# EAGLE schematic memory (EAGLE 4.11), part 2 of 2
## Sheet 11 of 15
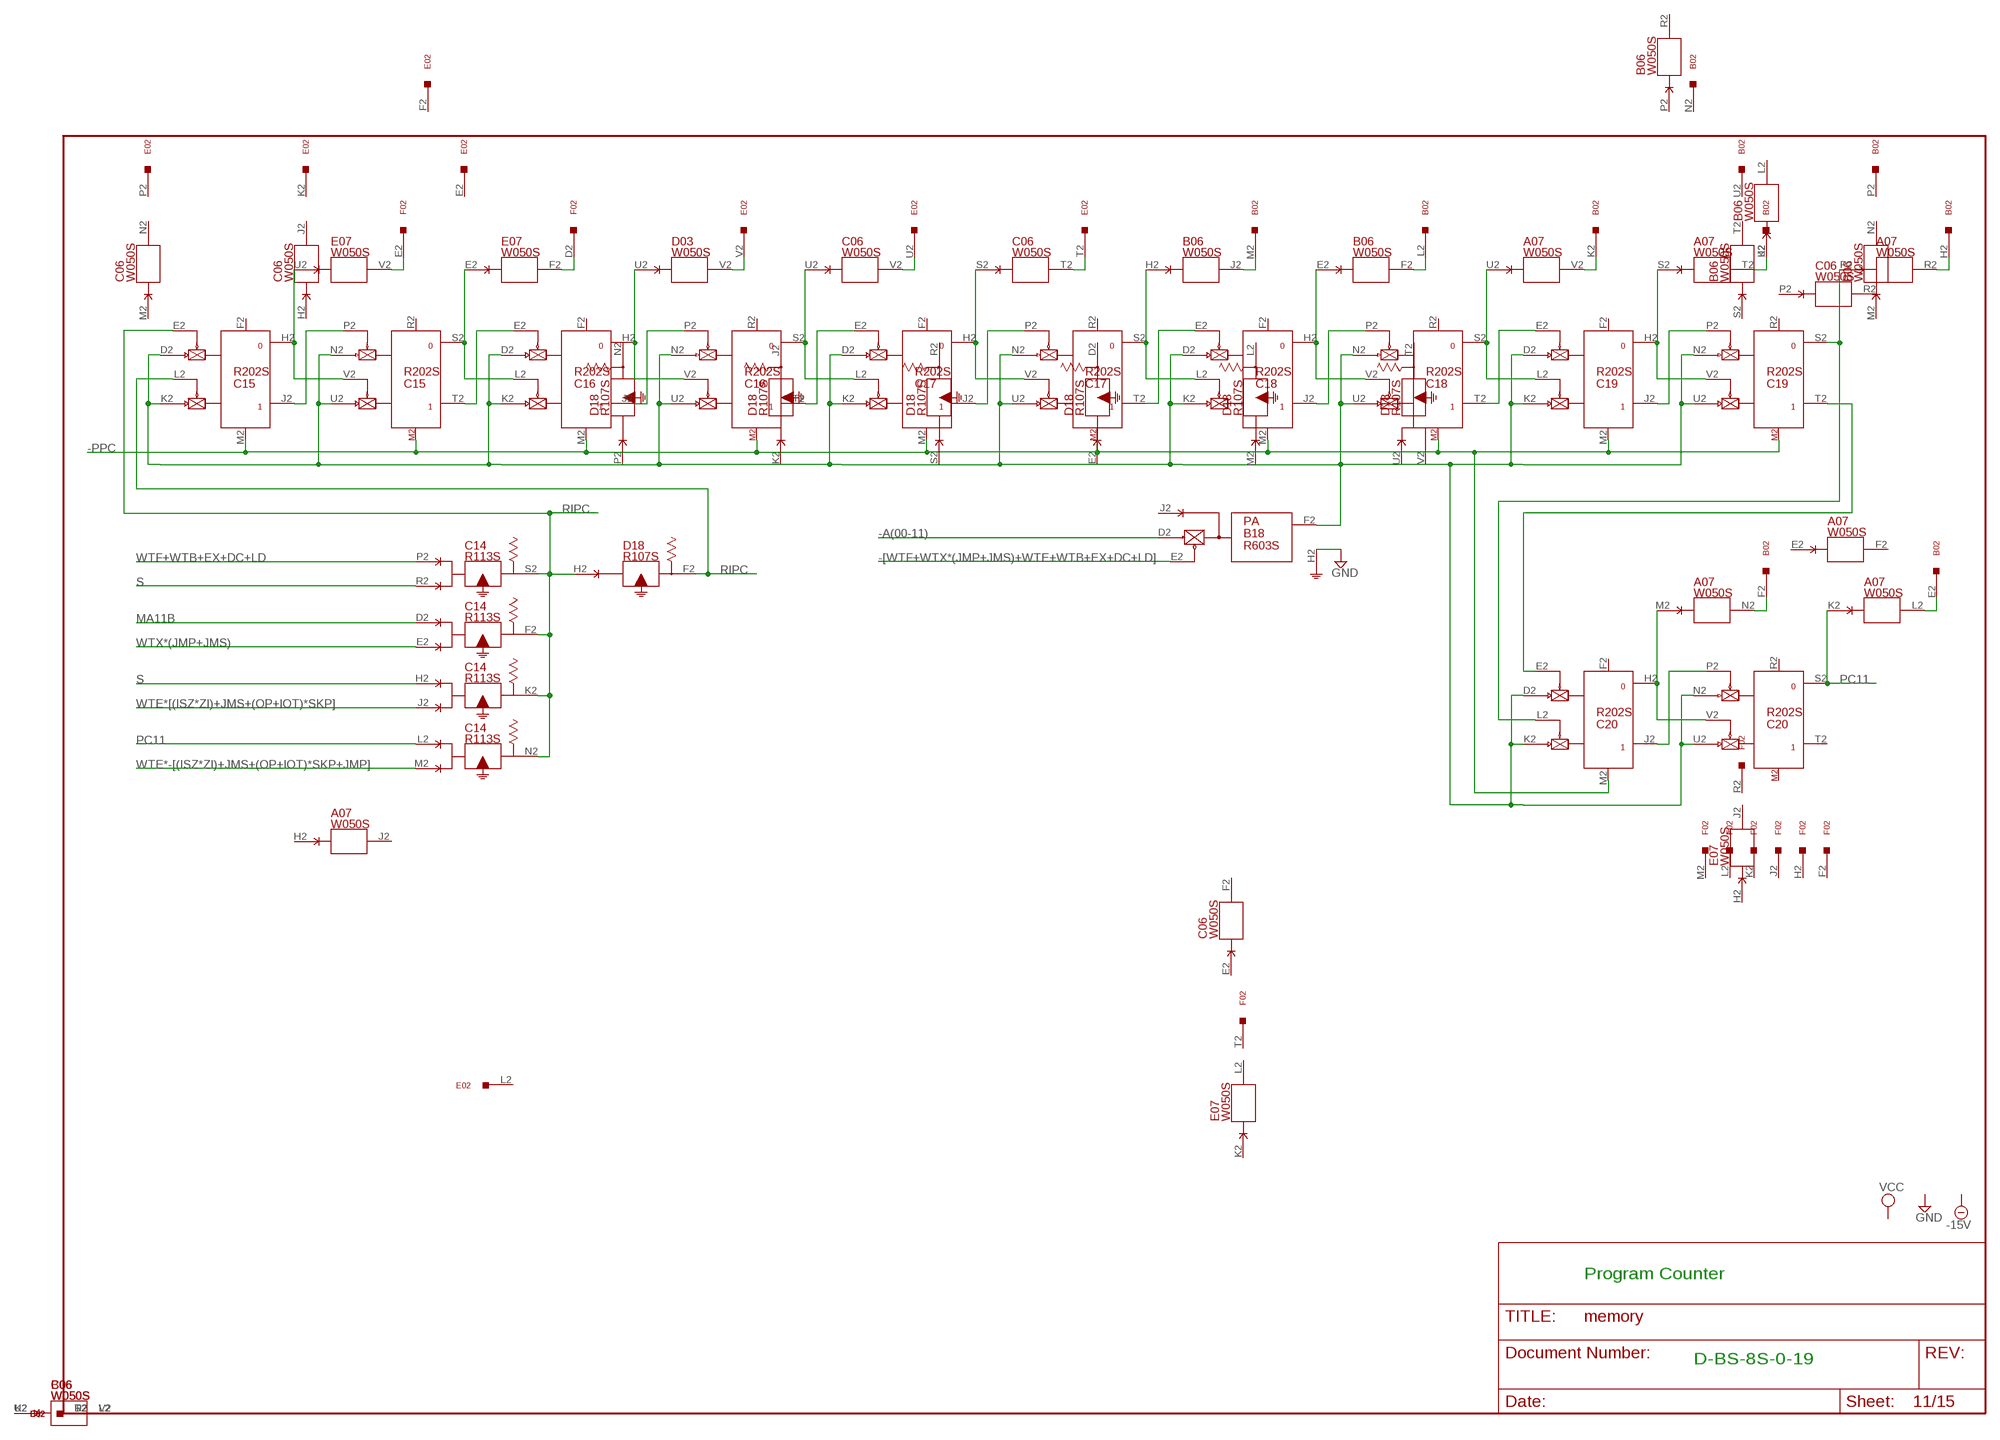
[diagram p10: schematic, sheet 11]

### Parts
C15  R202S  [H807S]
C16  R202S  [H807S]
C17  R202S  [H807S]
C18  R202S  [H807S]
C19  R202S  [H807S]
C20  R202S  [H807S]
D03  W050S  [H807S]

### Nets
-[WTF+WTX*(JMP+JMS)+WTE+WTB+EX+DC+LD]: B18.E2(F:EN0) ; also sheet 6
-A(00-11): B18.D2(F:PU0) ; also sheet 1,3,4,5,7,9,12
-PPC: C15.M2(J:SET) C16.M2(J:SET) C17.M2(J:SET) C18.M2(J:SET) C19.M2(J:SET) C20.M2(J:SET) ; also sheet 4,6,8,10,15
-RIPC: C14.F2(F:O$1) C14.K2(K:O$1) C14.N2(N:O$1) C14.S2(S:O$1) C15.E2(J:EN0) D18.H2(F:I$1)
GND [Supply]: B18.H2(F:G) ; also sheet 1,2,3,4,5,6,7,8,9,10,12,14,15
MA11B: C14.D2(F:I$1) ; also sheet 5
N$245: C15.H2 C15.V2(T:EN1) E07.U2(V:I$1)
N$246: C15.J2 C15.P2(T:EN0)
N$247: B18.F2(F:O) C15.D2(J:PU0) C15.K2(J:PU1) C15.N2(T:PU0) C15.U2(T:PU1) C16.D2(J:PU0) C16.K2(J:PU1) C16.N2(T:PU0) C16.U2(T:PU1) C17.D2(J:PU0) C17.K2(J:PU1) C17.N2(T:PU0) C17.U2(T:PU1) C18.D2(J:PU0) C18.K2(J:PU1) C18.N2(T:PU0) C18.U2(T:PU1) C19.D2(J:PU0) C19.K2(J:PU1) C19.N2(T:PU0) C19.U2(T:PU1) C20.D2(J:PU0) C20.K2(J:PU1) C20.N2(T:PU0) C20.U2(T:PU1)
N$248: C16.H2 C16.V2(T:EN1) D03.U2(V:I$1)
N$249: C16.J2 C16.P2(T:EN0)
N$250: A07.L2(L:O$1) B02.E2
N$251: C06.S2(T:I$1) C17.H2 C17.V2(T:EN1)
N$252: C17.J2 C17.P2(T:EN0)
N$253: A07.N2(N:O$1) B02.F2
N$254: B06.E2(F:I$1) C18.H2 C18.V2(T:EN1)
N$255: C18.J2 C18.P2(T:EN0)
N$256: A07.V2(V:O$1) B02.K2
N$257: A07.S2(T:I$1) C19.H2 C19.V2(T:EN1)
N$258: C19.J2 C19.P2(T:EN0)
N$259: A07.T2(T:O$1) B02.J2
N$260: A07.M2(N:I$1) C20.H2 C20.V2(T:EN1)
N$261: C20.J2 C20.P2(T:EN0)
N$262: A07.R2(R:O$1) B02.H2
N$263: C15.S2 C16.L2(J:EN1) E07.E2(F:I$1)
N$264: C15.T2 C16.E2(J:EN0)
N$265: C06.U2(V:I$1) C16.S2 C17.L2(J:EN1)
N$266: C16.T2 C17.E2(J:EN0)
N$267: B06.H2(J:I$1) C17.S2 C18.L2(J:EN1)
N$268: A07.U2(V:I$1) C18.S2 C19.L2(J:EN1)
N$269: C18.T2 C19.E2(J:EN0)
N$270: C17.T2 C18.E2(J:EN0)
N$271: A07.P2(R:I$1) C19.S2 C20.L2(J:EN1)
N$272: C19.T2 C20.E2(J:EN0)
N$273: B02.M2 B06.J2(J:O$1)
N$274: B02.L2 B06.F2(F:O$1)
N$275: D03.V2(V:O$1) E02.V2
N$276: C06.V2(V:O$1) E02.U2
N$277: C06.T2(T:O$1) E02.T2
N$278: E07.V2(V:O$1) F02.E2
N$279: E07.F2(F:O$1) F02.D2
PC11: A07.K2(L:I$1) C14.L2(N:I$1) C20.S2 ; also sheet 1,5,7
RIPC: C15.L2(J:EN1) D18.F2(F:O$1)
S: C14.H2(K:I$1) C14.R2(S:I$2) ; also sheet 1,5,7,12
WTE*-[(ISZ*ZI)+JMS+(OP+IOT)*SKP+JMP]: C14.M2(N:I$2) ; also sheet 5,6
WTE*[(ISZ*ZI)+JMS+(OP+IOT)*SKP]: C14.J2(K:I$2) ; also sheet 5,6
WTF+WTB+EX+DC+LD: C14.P2(S:I$1) ; also sheet 6
WTX*(JMP+JMS): C14.E2(F:I$2) ; also sheet 5,6,15
Unconnected: C15.F2(J:RESET) C15.R2(T:RESET) C16.F2(J:RESET) C16.R2(T:RESET) C17.F2(J:RESET) C17.R2(T:RESET) C18.F2(J:RESET) C18.R2(T:RESET) C19.F2(J:RESET) C19.R2(T:RESET) C20.F2(J:RESET) C20.R2(T:RESET) C20.T2 D18.V2(T:I$2)

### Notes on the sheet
- Program Counter
- D-BS-8S-0-19

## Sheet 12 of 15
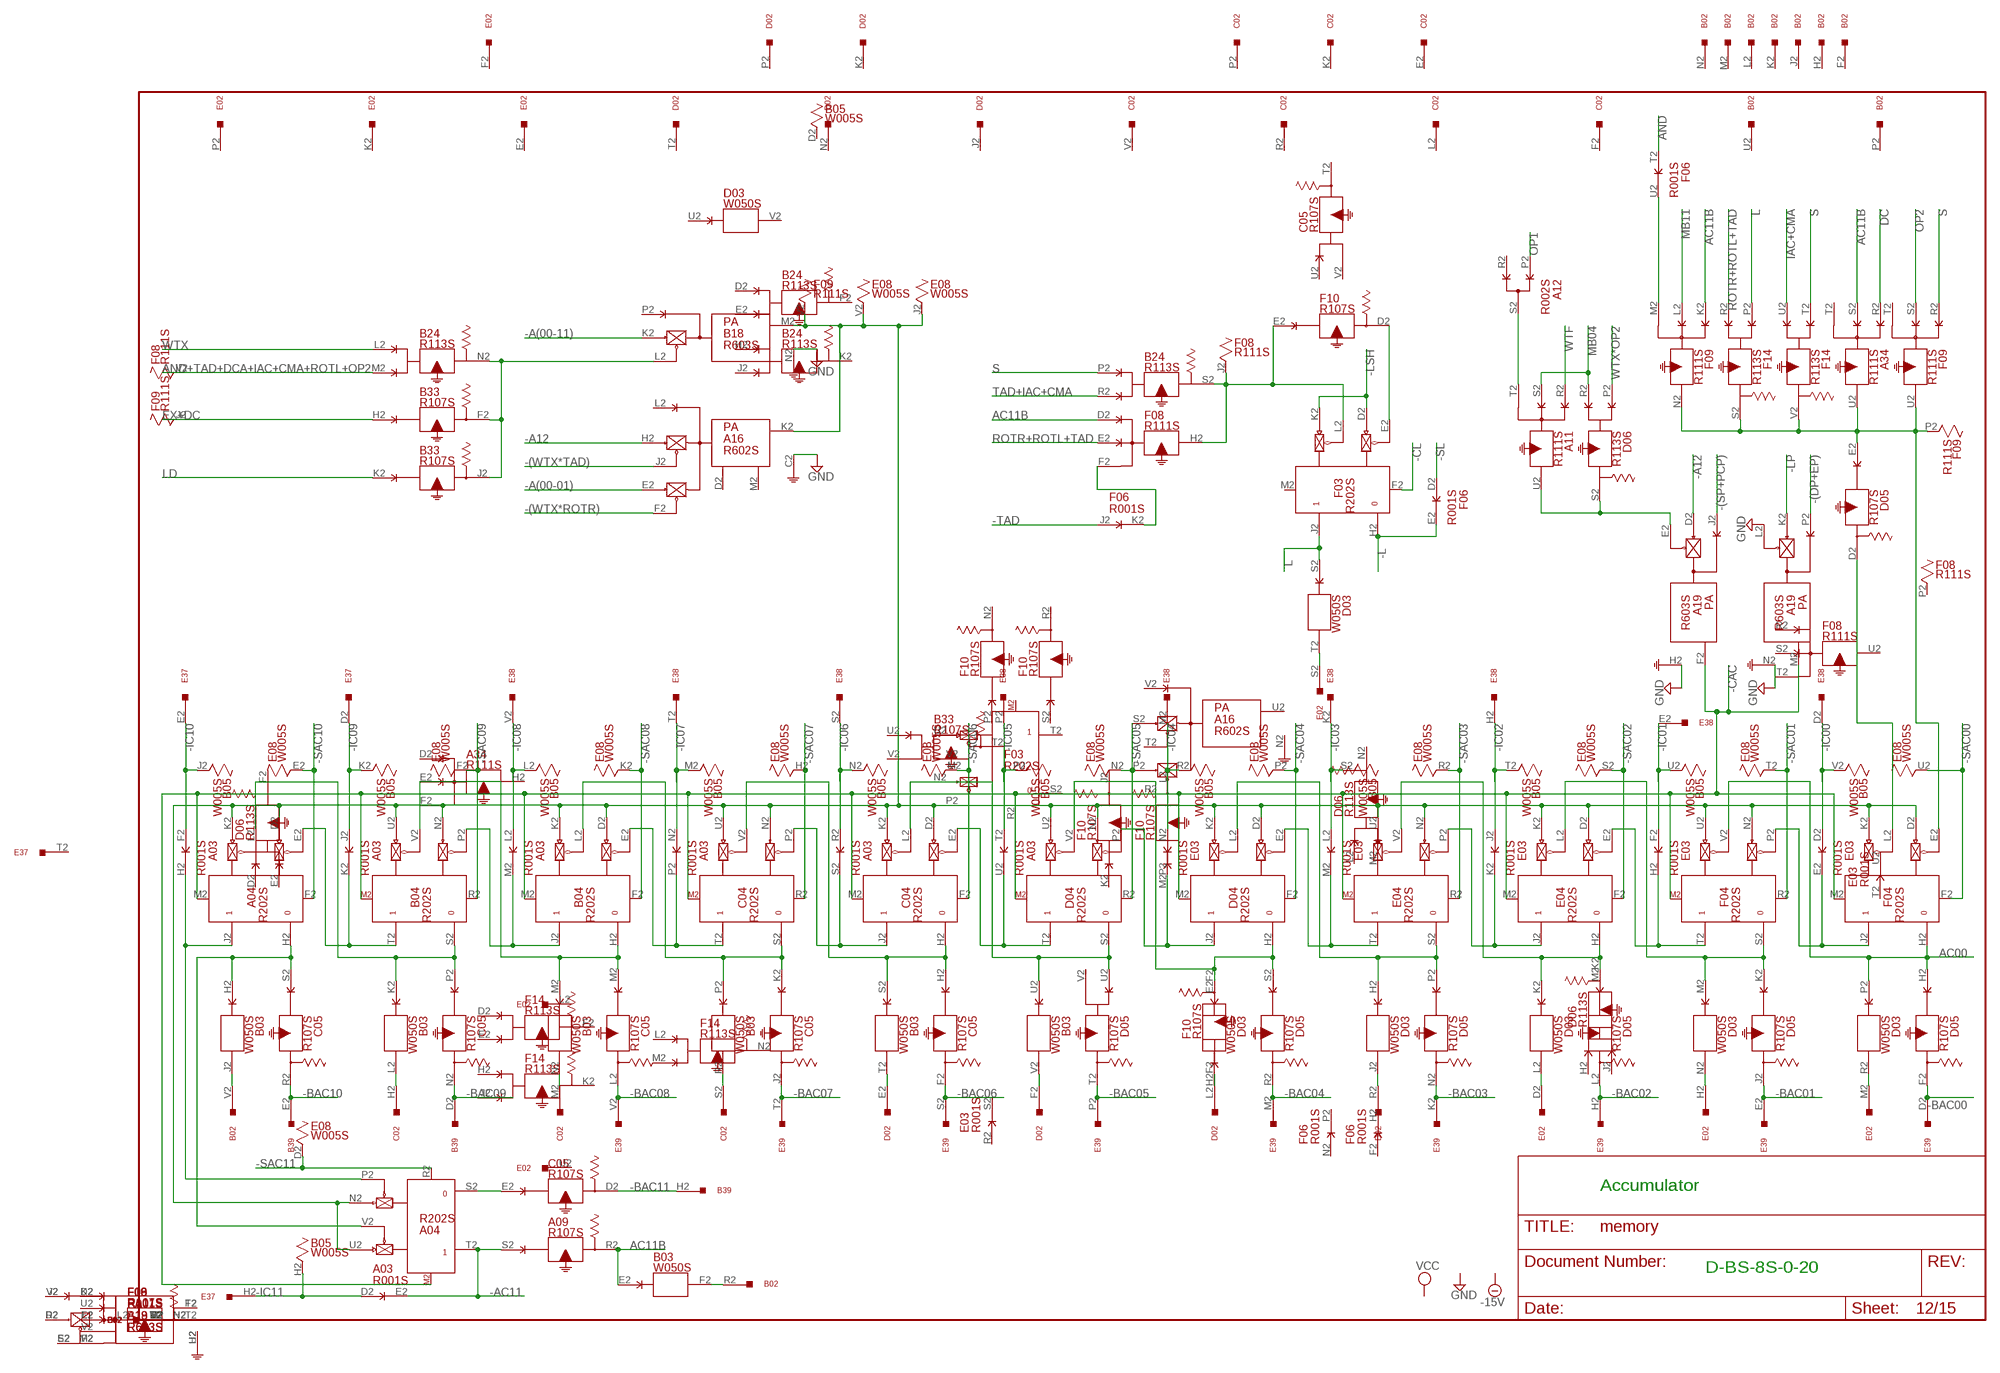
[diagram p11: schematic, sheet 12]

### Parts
A03  R001S  [H807S]
A04  R202S  [H807S]
A19  R603S  [H807S]
B03  W050S  [H807S]
B04  R202S  [H807S]
C04  R202S  [H807S]
D04  R202S  [H807S]
D05  R107S  [H807S]
E04  R202S  [H807S]
E08  W005S  [H807S]
E38  W028S  [H807S]
E39  W028S  [H807S]
F04  R202S  [H807S]

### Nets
-(DP+EP): A19.P2(M:I$1) ; also sheet 4,6,8
-(SP+PCP): A19.J2(F:I$1) ; also sheet 1,3,7,8,10,14,15
-(WTX*ROTR): A16.F2(K:F) ; also sheet 3,6
-(WTX*TAD): A16.J2(K:J) ; also sheet 6
-A12: A16.H2(K:H) A19.D2(F:PU0) ; also sheet 1,3,4,6,8,10,15
-A(00-01): A16.E2(K:E) ; also sheet 3,4
-A(00-11): B18.K2(M:PU0) ; also sheet 1,3,4,5,7,9,11
-AC11: A03.E2(E:E) A04.T2 A09.S2(R:I$1) ; also sheet 7
-BAC00: D05.F2(F:O$1) E39.D2
-BAC01: D05.J2(J:O$1) E39.E2
-BAC02: D05.L2(L:O$1) E39.H2
-BAC03: D05.N2(N:O$1) E39.K2
-BAC04: D05.R2(R:O$1) E39.M2
-BAC05: D05.T2(T:O$1) E39.P2
-BAC06: C05.F2(F:O$1) E39.S2
-BAC07: C05.J2(J:O$1) E39.T2
-BAC08: C05.L2(L:O$1) E39.V2
-BAC09: B39.D2 C05.N2(N:O$1)
-BAC10: B39.E2 C05.R2(R:O$1)
-BAC11: B39.H2 C05.D2(D:O$1)
-CAC: A04.M2(J:SET) A19.F2(F:O) A19.M2(M:O) B04.M2(J:SET) C04.M2(J:SET) D04.M2(J:SET) E04.M2(J:SET) F04.M2(J:SET) ; also sheet 10
-CL: F03.F2(J:RESET) ; also sheet 3
-IC00: B05.V2 E03.D2(E:D) E38.D2
-IC01: B05.U2 E03.F2(H:D) E38.E2
-IC02: B05.T2 E03.J2(K:D) E38.H2
-IC03: B05.S2 E03.L2(M:D) E38.K2
-IC04: B05.R2 E03.N2(P:D) E38.M2
-IC05: A03.T2(U:D) B05.P2 E38.P2
-IC06: A03.R2(S:D) B05.N2 E38.S2
-IC07: A03.N2(P:D) B05.M2 E38.T2
-IC08: A03.L2(M:D) B05.L2 E38.V2
-IC09: A03.J2(K:D) B05.K2 E37.D2
-IC10: A03.F2(H:D) B05.J2 E37.E2
-IC11: A03.D2(E:D) B05.H2 E37.H2
-L: F03.H2 F06.E2(E:E) ; also sheet 3
-LP: A19.K2(M:PU0) ; also sheet 4,6,8,15
-LSH: F03.D2(J:PU0) F03.K2(J:PU1) ; also sheet 3
-SAC00: E08.U2 F04.F2(J:RESET) ; also sheet 8
-SAC01: E08.T2 F04.R2(T:RESET) ; also sheet 8
-SAC02: E04.F2(J:RESET) E08.S2 ; also sheet 8
-SAC03: E04.R2(T:RESET) E08.R2 ; also sheet 8
-SAC04: D04.F2(J:RESET) E08.P2 ; also sheet 8
-SAC05: D04.R2(T:RESET) E08.N2 ; also sheet 8
-SAC06: C04.F2(J:RESET) E08.M2 ; also sheet 8
-SAC07: C04.R2(T:RESET) E08.H2 ; also sheet 8
-SAC08: B04.F2(J:RESET) E08.K2 ; also sheet 8
-SAC09: B04.R2(T:RESET) E08.F2 ; also sheet 8
-SAC10: A04.F2(J:RESET) E08.E2 ; also sheet 8
-SAC11: A04.R2(T:RESET) E08.D2 ; also sheet 8
-SL: F06.D2(E:D) ; also sheet 3
-TAD: F06.J2(K:D) ; also sheet 9
AC00: D03.P2(R:I$1) D05.H2(F:I$1) F04.H2 F04.V2(T:EN1) ; also sheet 3
AC11B: A09.R2(R:O$1) A34.S2(U:I$2) B03.E2(F:I$1) F08.D2(H:I$1) F09.K2(N:I$1) ; also sheet 1,7
AND: F06.T2(U:D) ; also sheet 9
AND+TAD+DCA+IAC+CMA+ROTL+OP2: B24.M2(N:I$2) ; also sheet 9
DC: A34.R2(U:I$1) ; also sheet 1,8
EX+DC: B33.H2(F:I$1) ; also sheet 5,7,8,9
GND [Supply]: A16.C2(K:GND) A19.H2(F:G) A19.L2(M:EN0) A19.N2(M:G) B18.N2(M:G) ; also sheet 1,2,3,4,5,6,7,8,9,10,11,14,15
IAC+CMA: F14.U2(V:I$2) ; also sheet 7,9
L: D03.S2(T:I$1) F03.J2 F14.P2(S:I$1) ; also sheet 3,7
LD: B33.K2(J:I$1) ; also sheet 7,8
MB04: A11.S2(U:I$2) D06.R2(S:I$2) ; also sheet 1
MB11: F09.L2(N:I$2) ; also sheet 1,5,6,7,9
N$281: D03.M2(N:I$1) D05.K2(J:I$1) E04.L2(J:EN1) F04.S2
N$282: B03.U2(V:I$1) C04.L2(J:EN1) D04.S2 D05.U2(T:I$1)
N$283: B02.R2 B03.F2(F:O$1)
N$284: D03.K2(L:I$1) D05.M2(L:I$1) E04.H2 E04.V2(T:EN1)
N$285: D03.E2(F:I$1) D04.H2 D04.V2(T:EN1) D05.S2(R:I$1)
N$286: D03.H2(J:I$1) D04.L2(J:EN1) D05.P2(N:I$1) E04.S2
N$287: B03.S2(T:I$1) C04.H2 C04.V2(T:EN1) C05.H2(F:I$1)
N$288: B03.P2(R:I$1) B04.L2(J:EN1) C04.S2 C05.K2(J:I$1)
N$289: A04.L2(J:EN1) B03.K2(L:I$1) B04.S2 C05.P2(N:I$1)
N$290: A04.H2 A04.V2(T:EN1) B03.H2(J:I$1) C05.S2(R:I$1)
N$291: B02.V2 B03.J2(J:O$1)
N$293: A04.S2 C05.E2(D:I$1)
N$294: B03.L2(L:O$1) C02.H2
N$295: B03.N2(N:O$1) C02.M2
N$296: B03.R2(R:O$1) C02.S2
N$297: B03.T2(T:O$1) D02.E2
N$298: B03.V2(V:O$1) D02.F2
N$299: D02.L2 D03.F2(F:O$1)
N$300: D02.R2 D03.J2(J:O$1)
N$301: D03.L2(L:O$1) E02.D2
N$302: D03.N2(N:O$1) E02.H2
N$303: D03.R2(R:O$1) E02.M2
N$304: E03.E2(E:E) F04.J2 F04.P2(T:EN0)
N$305: E03.H2(H:E) E04.E2(J:EN0) F04.T2
N$306: E03.K2(K:E) E04.J2 E04.P2(T:EN0)
N$307: D04.E2(J:EN0) E03.M2(M:E) E04.T2
N$308: A03.U2(U:E) C04.E2(J:EN0) D04.T2
N$309: D04.J2 D04.P2(T:EN0) E03.P2(P:E)
N$310: A03.S2(S:E) C04.J2 C04.P2(T:EN0)
N$311: A03.P2(P:E) B04.E2(J:EN0) C04.T2
N$312: A03.M2(M:E) B04.J2 B04.P2(T:EN0)
N$313: A03.K2(K:E) A04.E2(J:EN0) B04.T2
N$314: A03.H2(H:E) A04.J2 A04.P2(T:EN0)
N$315: A04.D2(J:PU0) A04.K2(J:PU1) A04.N2(T:PU0) A04.U2(T:PU1) A16.K2(K:K) B04.D2(J:PU0) B04.K2(J:PU1) B04.N2(T:PU0) B04.U2(T:PU1) B18.M2(M:O) C04.D2(J:PU0) C04.K2(J:PU1) C04.N2(T:PU0) C04.U2(T:PU1) D04.D2(J:PU0) D04.K2(J:PU1) D04.N2(T:PU0) D04.U2(T:PU1) E04.D2(J:PU0) E04.K2(J:PU1) E04.N2(T:PU0) E04.U2(T:PU1) E08.J2 E08.V2 F04.D2(J:PU0) F04.K2(J:PU1) F04.N2(T:PU0) F04.U2(T:PU1) F09.V2
N$317: B03.M2(N:I$1) B04.H2 B04.V2(T:EN1) C05.M2(L:I$1)
N$318: A34.U2(U:O$1) D05.E2(D:I$1) F04.E2(J:EN0) F09.N2(N:O$1) F09.P2 F09.U2(U:O$1) F14.S2(S:O$1) F14.V2(V:O$1)
N$319: D05.D2(D:O$1) F04.L2(J:EN1)
N$320: F06.U2(U:E) F09.M2(N:I$3)
N$321: A11.T2(U:I$3) A12.S2(S:F)
N$322: A11.U2(U:O$1) A19.E2(F:EN0) D06.S2(S:O$1)
N$323: D03.T2(T:O$1) E02.S2
N$326: F03.E2(J:EN0) F10.D2(D:O$1)
N$327: B24.S2(S:O$1) F03.L2(J:EN1) F08.H2(H:O$1) F08.J2 F10.E2(D:I$1)
N$328: F06.K2(K:E) F08.F2(H:I$3)
N$330: B18.L2(M:EN0) B24.N2(N:O$1) B33.F2(F:O$1) B33.J2(J:O$1)
OP1: A12.P2(S:D) ; also sheet 6,7,9
OP2: F09.S2(U:I$2) ; also sheet 3,6,7,8,9
ROTR+ROTL+TAD: F08.E2(H:I$2) F14.R2(S:I$2) ; also sheet 3,9
S: B24.P2(S:I$1) F09.R2(U:I$1) F14.T2(V:I$1) ; also sheet 1,5,7,11
TAD+IAC+CMA: B24.R2(S:I$2) ; also sheet 3,9
WTF: A11.R2(U:I$1) ; also sheet 1,3,5,6,8,10
WTX: B24.L2(N:I$1) ; also sheet 1,3,6,7,10,15
WTX*OP2: D06.P2(S:I$1) ; also sheet 6
Unconnected: A12.R2(S:E) A16.D2(K:D) A16.L2(K:L) A16.M2(K:M) A16.V2(U:L) A34.F2(H:I$3) A34.T2(U:I$3) B18.J2(F:I$1) B18.P2(M:I$1) C05.V2(T:I$2) D05.V2(T:I$2) D06.E2(F:I$2) E08.L2 F03.M2(J:SET) F03.T2 F08.T2(U:I$3) F09.F2(H:I$3) F09.T2(U:I$3) F10.V2(T:I$2)

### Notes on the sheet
- Accumulator
- D-BS-8S-0-20

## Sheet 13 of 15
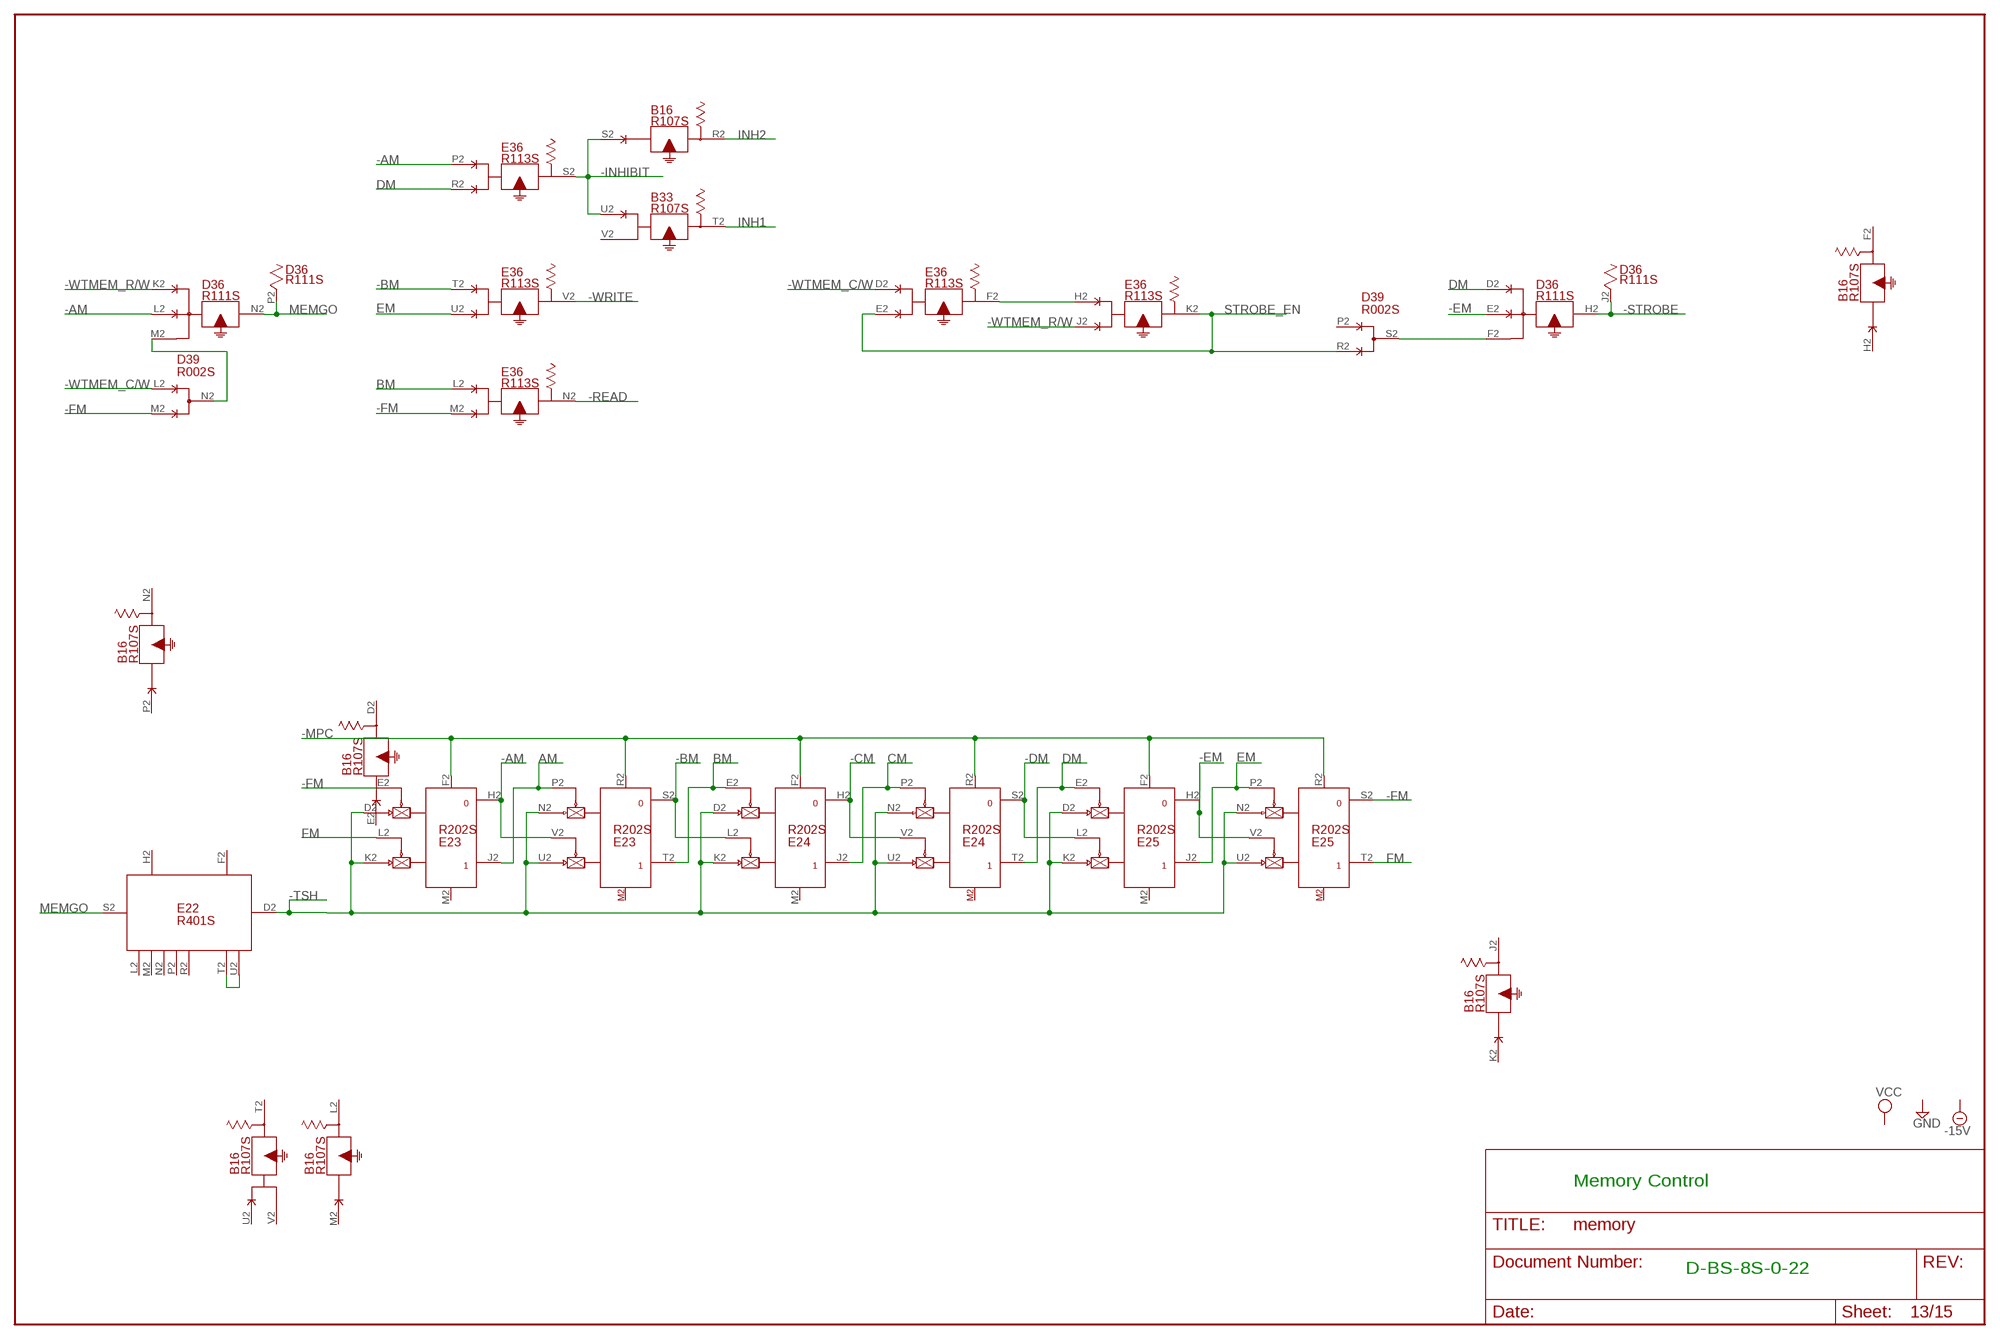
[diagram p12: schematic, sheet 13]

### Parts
E22  R401S  [H807S]
E23  R202S  [H807S]
E24  R202S  [H807S]
E25  R202S  [H807S]
E36  R113S  [H807S]

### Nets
-AM: D36.L2(N:I$2) E23.H2 E23.V2(T:EN1) E36.P2(S:I$1)
-BM: E23.S2 E24.L2(J:EN1) E36.T2(V:I$1)
-CM: E24.H2 E24.V2(T:EN1)
-DM: E24.S2 E25.L2(J:EN1)
-EM: D36.E2(H:I$2) E25.H2 E25.V2(T:EN1)
-FM: D39.M2(N:E) E23.E2(J:EN0) E25.S2 E36.M2(N:I$2)
-INHIBIT: B16.S2(R:I$1) B33.U2(T:I$1) E36.S2(S:O$1)
-MPC: E23.F2(J:RESET) E23.R2(T:RESET) E24.F2(J:RESET) E24.R2(T:RESET) E25.F2(J:RESET) E25.R2(T:RESET) ; also sheet 10,14
-READ: E36.N2(N:O$1) ; also sheet 2
-STROBE: D36.H2(H:O$1) D36.J2 ; also sheet 2
-TSH: E22.D2(D) E23.D2(J:PU0) E23.K2(J:PU1) E23.N2(T:PU0) E23.U2(T:PU1) E24.D2(J:PU0) E24.K2(J:PU1) E24.N2(T:PU0) E24.U2(T:PU1) E25.D2(J:PU0) E25.K2(J:PU1) E25.N2(T:PU0) E25.U2(T:PU1)
-WRITE: E36.V2(V:O$1)
-WTMEM_C/W: D39.L2(N:D) E36.D2(F:I$1) ; also sheet 6
-WTMEM_R/W: D36.K2(N:I$1) E36.J2(K:I$2) ; also sheet 1,6
AM: E23.J2 E23.P2(T:EN0)
BM: E23.T2 E24.E2(J:EN0) E36.L2(N:I$1)
CM: E24.J2 E24.P2(T:EN0)
DM: D36.D2(H:I$1) E24.T2 E25.E2(J:EN0) E36.R2(S:I$2)
EM: E25.J2 E25.P2(T:EN0) E36.U2(V:I$2)
FM: E23.L2(J:EN1) E25.T2
INH1: B33.T2(T:O$1) ; also sheet 2
INH2: B16.R2(R:O$1)
MEMGO: D36.N2(N:O$1) D36.P2 E22.S2(S) ; also sheet 6
N$329: E22.T2(T) E22.U2(U)
N$331: D36.F2(H:I$3) D39.S2(S:F)
N$332: D36.M2(N:I$3) D39.N2(N:F)
N$334: E36.F2(F:O$1) E36.H2(K:I$1)
STROBE_EN: D39.R2(S:E) E36.E2(F:I$2) E36.K2(K:O$1)
Unconnected: B16.V2(T:I$2) B33.V2(T:I$2) E22.F2(F) E22.H2(H) E22.L2(L) E22.M2(M) E22.N2(N) E22.P2(P) E22.R2(R) E23.M2(J:SET) E24.M2(J:SET) E25.M2(J:SET)

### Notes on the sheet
- Memory Control
- D-BS-8S-0-22

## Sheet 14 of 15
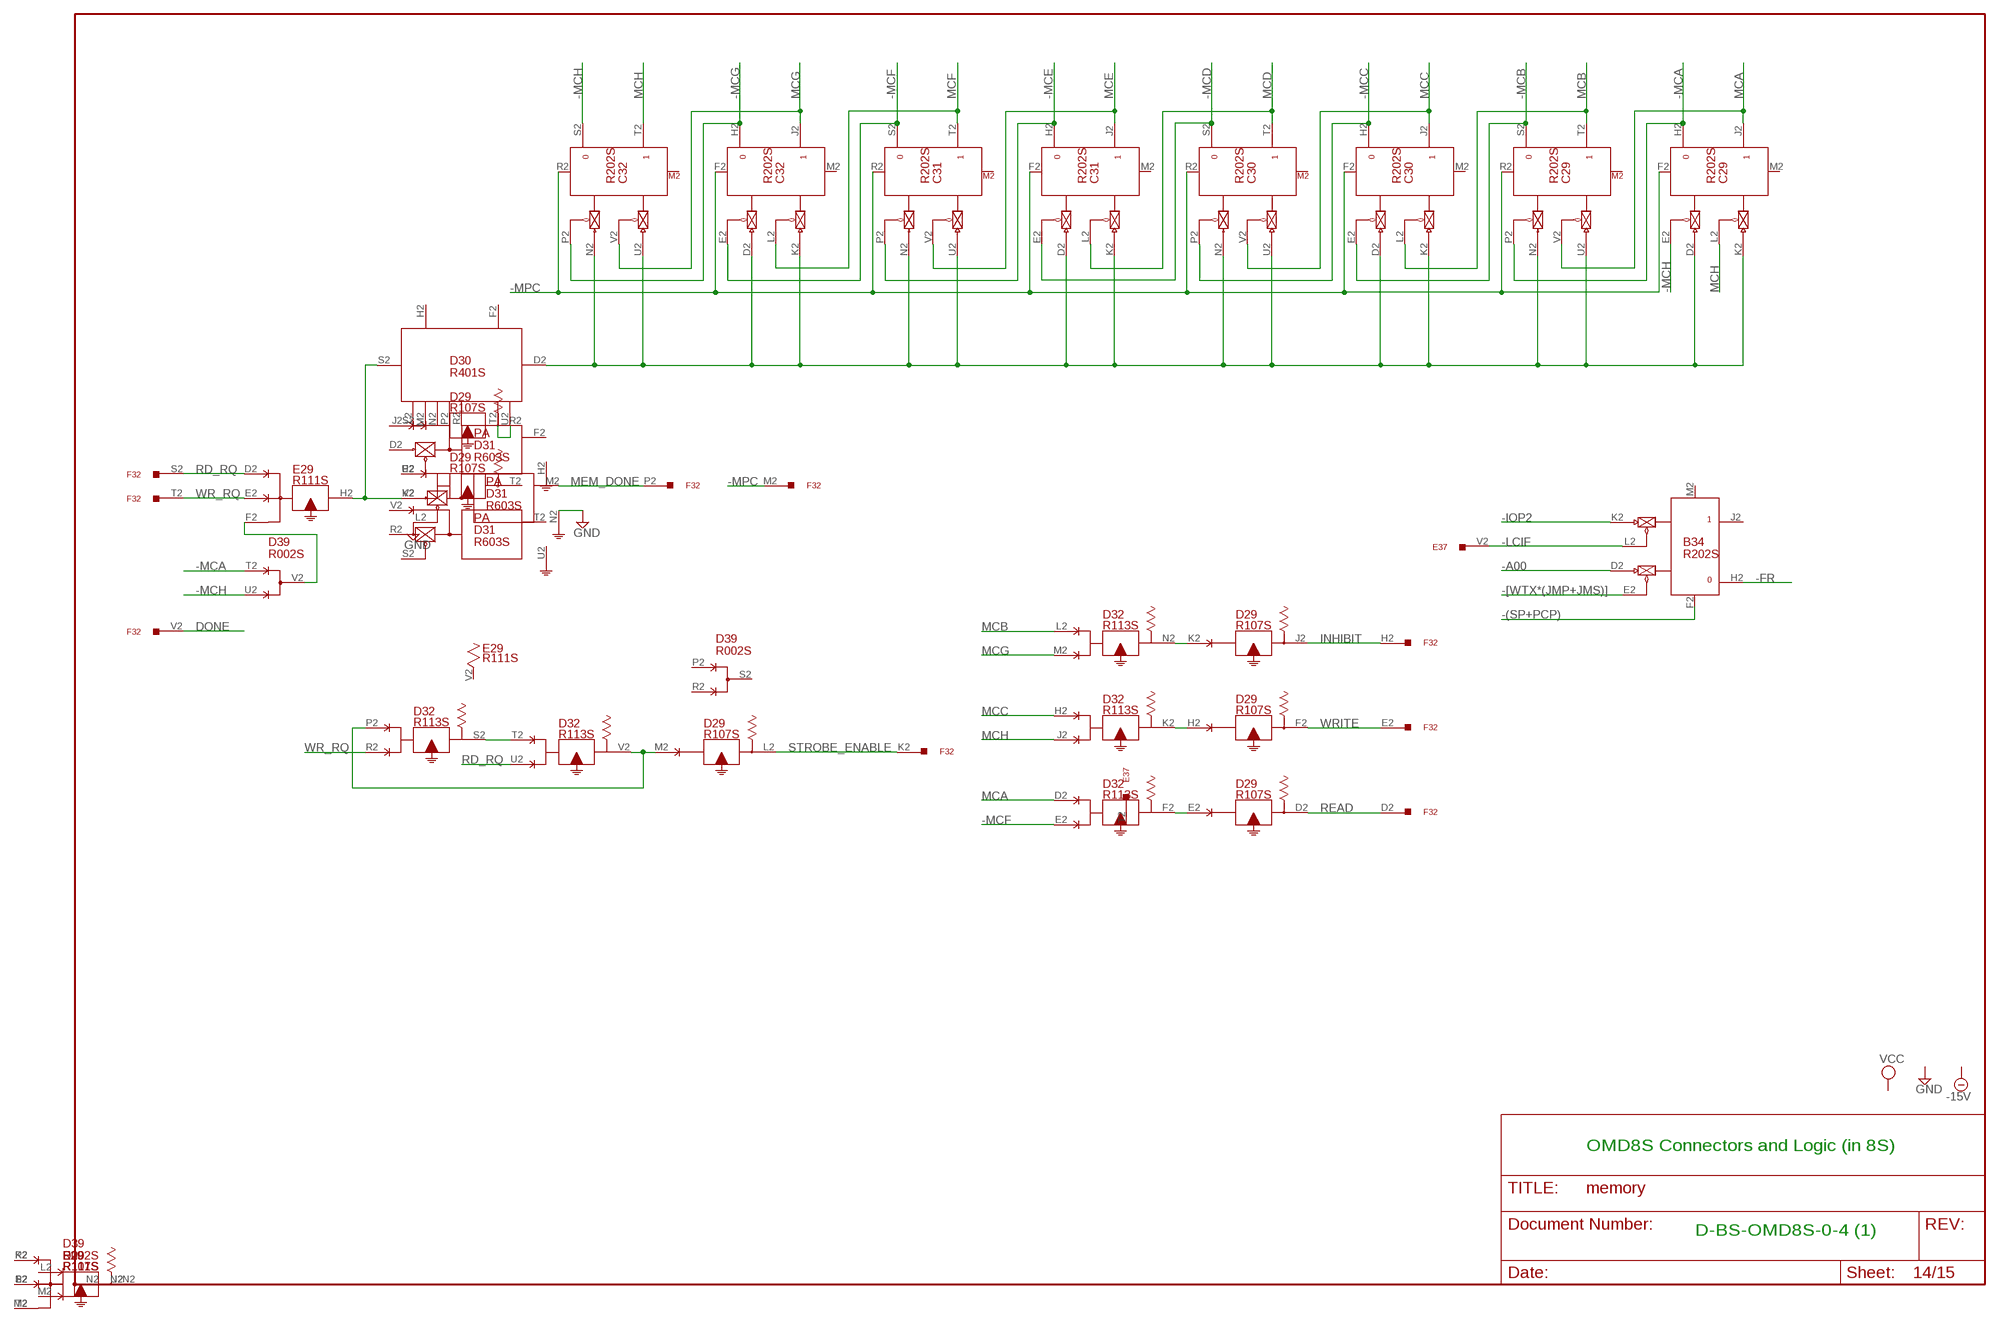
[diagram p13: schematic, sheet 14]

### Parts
C29  R202S  [H807S]
C30  R202S  [H807S]
C31  R202S  [H807S]
C32  R202S  [H807S]
D29  R107S  [H807S]
D30  R401S  [H807S]
D31  R603S  [H807S]
D32  R113S  [H807S]
E29  R111S  [H807S]
F32  W021S  [H807S]

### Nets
-(SP+PCP): B34.F2(J:RESET) ; also sheet 1,3,7,8,10,12,15
-[WTX*(JMP+JMS)]: B34.E2(J:EN0) ; also sheet 6
-A00: B34.D2(J:PU0) ; also sheet 3,4,5,9,10,15
-FR: B34.H2 ; also sheet 10
-IOP2: B34.K2(J:PU1) ; also sheet 10
-LCIF: B34.L2(J:EN1) E37.V2
-MCA: C29.H2 C29.P2(T:EN0) D39.T2(V:D)
-MCB: C29.S2 C30.E2(J:EN0)
-MCC: C30.H2 C30.P2(T:EN0)
-MCD: C30.S2 C31.E2(J:EN0)
-MCE: C31.H2 C31.P2(T:EN0)
-MCF: C31.S2 C32.E2(J:EN0) D32.E2(F:I$2)
-MCG: C32.H2 C32.P2(T:EN0)
-MCH: C29.E2(J:EN0) C32.S2 D39.U2(V:E)
-MPC: C29.F2(J:RESET) C29.R2(T:RESET) C30.F2(J:RESET) C30.R2(T:RESET) C31.F2(J:RESET) C31.R2(T:RESET) C32.F2(J:RESET) C32.R2(T:RESET) F32.M2 ; also sheet 10,13
DONE: F32.V2
GND [Supply]: D31.L2(M:EN0) D31.N2(M:G) ; also sheet 1,2,3,4,5,6,7,8,9,10,11,12,15
INHIBIT: D29.J2(J:O$1) F32.H2
MCA: C29.J2 C29.V2(T:EN1) D32.D2(F:I$1)
MCB: C29.T2 C30.L2(J:EN1) D32.L2(N:I$1)
MCC: C30.J2 C30.V2(T:EN1) D32.H2(K:I$1)
MCD: C30.T2 C31.L2(J:EN1)
MCE: C31.J2 C31.V2(T:EN1)
MCF: C31.T2 C32.L2(J:EN1)
MCG: C32.J2 C32.V2(T:EN1) D32.M2(N:I$2)
MCH: C29.L2(J:EN1) C32.T2 D32.J2(K:I$2)
MEM_DONE: D31.M2(M:O) F32.P2
N$43: D39.V2(V:F) E29.F2(H:I$3)
N$45: D30.T2(T) D30.U2(U)
N$70: D30.S2(S) D31.K2(M:PU0) E29.H2(H:O$1)
N$80: C29.D2(J:PU0) C29.K2(J:PU1) C29.N2(T:PU0) C29.U2(T:PU1) C30.D2(J:PU0) C30.K2(J:PU1) C30.N2(T:PU0) C30.U2(T:PU1) C31.D2(J:PU0) C31.K2(J:PU1) C31.N2(T:PU0) C31.U2(T:PU1) C32.D2(J:PU0) C32.K2(J:PU1) C32.N2(T:PU0) C32.U2(T:PU1) D30.D2(D)
N$85: D29.M2(L:I$1) D32.P2(S:I$1) D32.V2(V:O$1)
N$91: D32.S2(S:O$1) D32.T2(V:I$1)
N$93: D29.E2(D:I$1) D32.F2(F:O$1)
N$96: D29.H2(F:I$1) D32.K2(K:O$1)
N$98: D29.K2(J:I$1) D32.N2(N:O$1)
RD_RQ: D32.U2(V:I$2) E29.D2(H:I$1) F32.S2
READ: D29.D2(D:O$1) F32.D2 ; also sheet 15
STROBE_ENABLE: D29.L2(L:O$1) F32.K2
WR_RQ: D32.R2(S:I$2) E29.E2(H:I$2) F32.T2
WRITE: D29.F2(F:O$1) F32.E2 ; also sheet 15
Unconnected: B34.J2 B34.M2(J:SET) C29.M2(J:SET) C30.M2(J:SET) C31.M2(J:SET) C32.M2(J:SET) D30.F2(F) D30.H2(H) D30.L2(L) D30.M2(M) D30.N2(N) D30.P2(P) D30.R2(R) D31.P2(M:I$1) D39.P2(S:D) E29.J2 E29.P2

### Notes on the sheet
- OMD8S Connectors and Logic (in 8S)
- D-BS-OMD8S-0-4 (1)

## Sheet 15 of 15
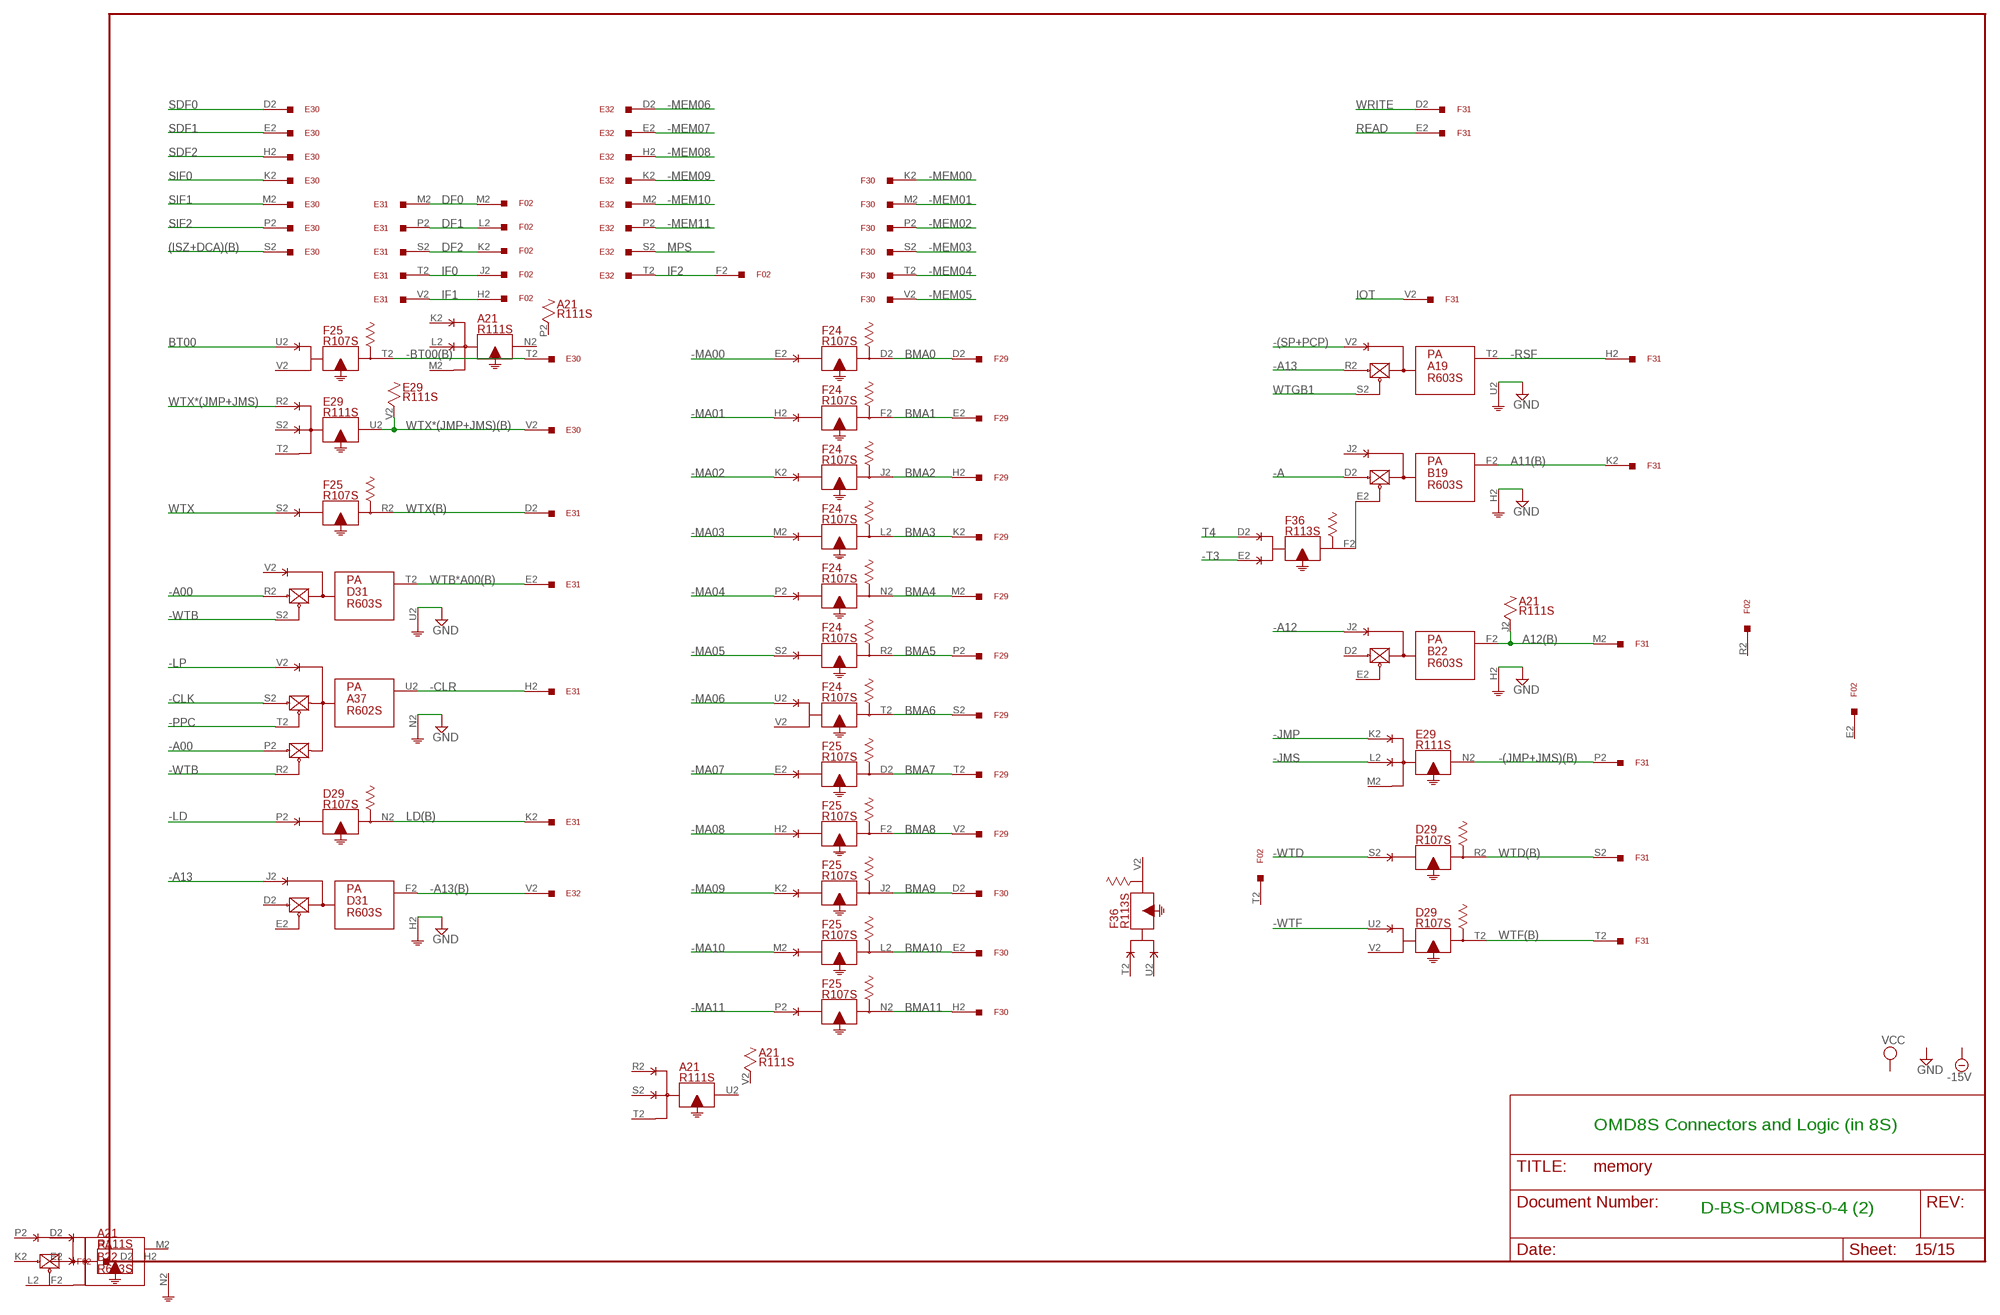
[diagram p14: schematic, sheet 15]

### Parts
E30  W021S  [H807S]
E31  W021S  [H807S]
E32  W021S  [H807S]
F24  R107S  [H807S]
F25  R107S  [H807S]
F29  W021S  [H807S]
F30  W021S  [H807S]
F31  W021S  [H807S]

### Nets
(ISZ+DCA)(B): E30.S2
-(JMP+JMS)(B): E29.N2(N:O$1) F31.P2
-(SP+PCP): A19.V2(T:I$1) ; also sheet 1,3,7,8,10,12,14
-A: B19.D2(F:PU0) ; also sheet 4
-A00: A37.P2(U:E) D31.R2(T:PU0) ; also sheet 3,4,5,9,10,14
-A12: B22.J2(F:I$1) ; also sheet 1,3,4,6,8,10,12
-A13: A19.R2(T:PU0) D31.J2(F:I$1) ; also sheet 1,4,5,6,7,10
-A13(B): D31.F2(F:O) E32.V2
-BT00(B): E30.T2 F25.T2(T:O$1)
-CLK: A37.S2(U:H) ; also sheet 4,8
-CLR: A37.U2(U:K) E31.H2
-JMP: E29.K2(N:I$1) ; also sheet 9
-JMS: E29.L2(N:I$2) ; also sheet 9
-LD: D29.P2(N:I$1) ; also sheet 6,8
-LP: A37.V2(U:L) ; also sheet 4,6,8,12
-MA00: F24.E2(D:I$1) ; also sheet 2,5
-MA01: F24.H2(F:I$1) ; also sheet 2,5
-MA02: F24.K2(J:I$1) ; also sheet 2,5
-MA03: F24.M2(L:I$1) ; also sheet 2,5
-MA04: F24.P2(N:I$1) ; also sheet 2,5,6
-MA05: F24.S2(R:I$1) ; also sheet 2,5
-MA06: F24.U2(T:I$1) ; also sheet 2,5
-MA07: F25.E2(D:I$1) ; also sheet 2,5
-MA08: F25.H2(F:I$1) ; also sheet 2,5
-MA09: F25.K2(J:I$1) ; also sheet 2,5
-MA10: F25.M2(L:I$1) ; also sheet 2,5
-MA11: F25.P2(N:I$1) ; also sheet 2,5
-MEM00: F30.K2 ; also sheet 1,2
-MEM01: F30.M2 ; also sheet 1,2
-MEM02: F30.P2 ; also sheet 1,2
-MEM03: F30.S2 ; also sheet 1,2
-MEM04: F30.T2 ; also sheet 1,2
-MEM05: F30.V2 ; also sheet 1,2
-MEM06: E32.D2 ; also sheet 1,2
-MEM07: E32.E2 ; also sheet 1,2
-MEM08: E32.H2 ; also sheet 1,2
-MEM09: E32.K2 ; also sheet 1,2
-MEM10: E32.M2 ; also sheet 1,2
-MEM11: E32.P2 ; also sheet 1,2
-PPC: A37.T2(U:J) ; also sheet 4,6,8,10,11
-RSF: A19.T2(T:O) F31.H2
-T3: F36.E2(F:I$2) ; also sheet 4
-WTB: A37.R2(U:F) D31.S2(T:EN0) ; also sheet 6,9
-WTD: D29.S2(R:I$1) ; also sheet 6
-WTF: D29.U2(T:I$1) ; also sheet 6,7,9
A11(B): B19.F2(F:O) F31.K2
A12(B): A21.J2 B22.F2(F:O) F31.M2
BMA0: F24.D2(D:O$1) F29.D2
BMA1: F24.F2(F:O$1) F29.E2
BMA2: F24.J2(J:O$1) F29.H2
BMA3: F24.L2(L:O$1) F29.K2
BMA4: F24.N2(N:O$1) F29.M2
BMA5: F24.R2(R:O$1) F29.P2
BMA6: F24.T2(T:O$1) F29.S2
BMA7: F25.D2(D:O$1) F29.T2
BMA8: F25.F2(F:O$1) F29.V2
BMA9: F25.J2(J:O$1) F30.D2
BMA10: F25.L2(L:O$1) F30.E2
BMA11: F25.N2(N:O$1) F30.H2
BT00: F25.U2(T:I$1) ; also sheet 4,7,9
DF0: E31.M2 F02.M2
DF1: E31.P2 F02.L2
DF2: E31.S2 F02.K2
GND [Supply]: A19.U2(T:G) A37.N2(U:C) B19.H2(F:G) B22.H2(F:G) D31.H2(F:G) D31.U2(T:G) ; also sheet 1,2,3,4,5,6,7,8,9,10,11,12,14
IF0: E31.T2 F02.J2
IF1: E31.V2 F02.H2
IF2: E32.T2 F02.F2
IOT: F31.V2 ; also sheet 9,10
LD(B): D29.N2(N:O$1) E31.K2
MPS: E32.S2
N$119: B19.E2(F:EN0) F36.F2(F:O$1)
READ: F31.E2 ; also sheet 14
SDF0: E30.D2 ; also sheet 8
SDF1: E30.E2 ; also sheet 8
SDF2: E30.H2 ; also sheet 8
SIF0: E30.K2 ; also sheet 8
SIF1: E30.M2 ; also sheet 8
SIF2: E30.P2 ; also sheet 8
T4: F36.D2(F:I$1) ; also sheet 4
WRITE: F31.D2 ; also sheet 14
WTB*A00(B): D31.T2(T:O) E31.E2
WTD(B): D29.R2(R:O$1) F31.S2
WTF(B): D29.T2(T:O$1) F31.T2
WTGB1: A19.S2(T:EN0)
WTX: F25.S2(R:I$1) ; also sheet 1,3,6,7,10,12
WTX(B): E31.D2 F25.R2(R:O$1)
WTX*(JMP+JMS): E29.R2(U:I$1) ; also sheet 5,6,11
WTX*(JMP+JMS)(B): E29.U2(U:O$1) E29.V2 E30.V2
Unconnected: B19.J2(F:I$1) B22.D2(F:PU0) B22.E2(F:EN0) B22.P2(M:I$1) D29.V2(T:I$2) D31.D2(F:PU0) D31.E2(F:EN0) D31.V2(T:I$1) E29.M2(N:I$3) E29.S2(U:I$2) E29.T2(U:I$3) F24.V2(T:I$2) F25.V2(T:I$2) F36.T2(V:I$1)

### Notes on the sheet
- OMD8S Connectors and Logic (in 8S)
- D-BS-OMD8S-0-4 (2)

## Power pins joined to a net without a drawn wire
-15V: A03.B2(-15V) A04.B2(-15V) A05.B2(-15V) A06.B2(-15V) A07.B2(-15V) A08.B2(-15V) A09.B2(-15V) A10.B2(-15V) A11.B2(-15V) A12.B2(-15V) A13.B2(-15V) A14.B2(-15V) A15.B2(-15V) A16.B2(-15V) A17.B2(-15V) A18.B2(-15V) A19.B2(-15V) A20.B2(-15V) A21.B2(-15V) A22.B2(-15V) A23.B2(-15V) A24.B2(-15V) A25.B2(-15V) A26.B2(-15V) A27.B2(-15V) A28.B2(-15V) A29.B2(-15V) A30.B2(-15V) A31.B2(-15V) A32.B2(-15V) A33.B2(-15V) A34.B2(-15V) A35.B2(-15V) A36.B2(-15V) A37.B2(-15V) A38.B2(-15V) A39.B2(-15V) A40.B2(-15V) B03.B2(-15V) B04.B2(-15V) B05.B2(-15V) B06.B2(-15V) B07.B2(-15V) B08.B2(-15V) B09.B2(-15V) B10.B2(-15V) B11.B2(-15V) B12.B2(-15V) B13.B2(-15V) B14.B2(-15V) B15.B2(-15V) B16.B2(-15V) B17.B2(-15V) B18.B2(-15V) B19.B2(-15V) B20.B2(-15V) B21.B2(-15V) B22.B2(-15V) B23.B2(-15V) B24.B2(-15V) B25.B2(-15V) B26.B2(-15V) B27.B2(-15V) B28.B2(-15V) B29.B2(-15V) B30.B2(-15V) B31.B2(-15V) B32.B2(-15V) B33.B2(-15V) B34.B2(-15V) B35.B2(-15V) B36.B2(-15V) B37.B2(-15V) B38.B2(-15V) B40.B2(-15V) C03.B2(-15V) C04.B2(-15V) C05.B2(-15V) C06.B2(-15V) C07.B2(-15V) C08.B2(-15V) C09.B2(-15V) C10.B2(-15V) C11.B2(-15V) C12.B2(-15V) C13.B2(-15V) C14.B2(-15V) C15.B2(-15V) C16.B2(-15V) C17.B2(-15V) C18.B2(-15V) C19.B2(-15V) C20.B2(-15V) C21.B2(-15V) C22.B2(B:-15V) C23.B2(-15V) C24.B2(-15V) C25.B2(B:-15V) C26.B2(-15V) C27.B2(B:-15V) C29.B2(-15V) C30.B2(-15V) C31.B2(-15V) C32.B2(-15V) C33.B2 C34.B2 C35.B2 C36.B2(-15V) C37.B2(-15V) C38.B2(-15V) C39.B2(-15V) C40.B2(-15V) D03.B2(-15V) D04.B2(-15V) D05.B2(-15V) D06.B2(-15V) D07.B2(-15V) D08.B2(-15V) D09.B2(-15V) D10.B2(-15V) D11.B2(-15V) D12.B2(-15V) D13.B2(-15V) D14.B2(-15V) D15.B2(-15V) D16.B2(-15V) D17.B2(-15V) D18.B2(-15V) D19.B2(-15V) D20.B2(-15V) D21.B2(-15V) D22.B2(-15V) D23.B2 D24.B2 D25.B2 D26.B2 D27.B2(-15V) D29.B2(-15V) D30.B2(-15V) D31.B2(-15V) D32.B2(-15V) D33.B2 D34.B2 D35.B2 D36.B2(-15V) D37.B2(-15V) D38.B2(-15V) D39.B2(-15V) E03.B2(-15V) E04.B2(-15V) E05.B2(-15V) E06.B2(-15V) E07.B2(-15V) E08.B2(-15V) E09.B2(-15V) E10.B2(-15V) E11.B2(-15V) E12.B2(-15V) E13.B2(-15V) E14.B2(-15V) E15.B2(-15V) E16.B2(-15V) E17.B2(-15V) E18.B2(-15V) E19.B2(-15V) E20.B2(-15V) E21.B2 E22.B2(-15V) E23.B2(-15V) E24.B2(-15V) E25.B2(-15V) E26.B2 E27.B2 E28.B2 E29.B2(-15V) E33.B2 E34.B2 E35.B2 E36.B2(-15V) F03.B2(-15V) F04.B2(-15V) F05.B2(-15V) F06.B2(-15V) F07.B2(-15V) F08.B2(-15V) F09.B2(-15V) F10.B2(-15V) F11.B2(-15V) F12.B2(-15V) F13.B2(-15V) F14.B2(-15V) F15.B2(-15V) F16.B2(-15V) F17.B2(-15V) F18.B2(-15V) F19.B2(-15V) F20.B2(-15V) F21.B2 F22.B2(-15V) F23.B2(-15V) F24.B2(-15V) F25.B2(-15V) F26.B2 F27.B2 F28.B2 F33.B2 F34.B2 F35.B2 F36.B2(-15V) F37.B2(-15V) F38.B2(-15V) F39.B2(-15V) F40.B2(-15V)
GND: A03.C2(GND) A04.C2(GND) A05.C2(GND) A06.C2(GND) A07.C2(GND) A08.C2(GND) A09.C2(GND) A10.C2(GND) A11.C2(GND) A12.C2(GND) A13.C2(GND) A14.C2(GND) A15.C2(GND) A17.C2(GND) A18.C2(GND) A19.C2(GND) A20.C2(GND) A21.C2(GND) A22.C2(GND) A23.C2(GND) A24.C2(GND) A25.C2(GND) A26.C2(GND) A27.C2(GND) A29.C2(GND) A30.C2(GND) A31.C2(GND) A32.C2(GND) A33.C2(GND) A34.C2(GND) A35.C2(GND) A36.C2(GND) A38.C2(GND) A39.C2(GND) A40.C2(GND) B03.C2(GND) B04.C2(GND) B05.C2(GND) B06.C2(GND) B07.C2(GND) B08.C2(GND) B09.C2(GND) B10.C2(GND) B11.C2(GND) B12.C2(GND) B13.C2(GND) B14.C2(GND) B15.C2(GND) B16.C2(GND) B17.C2(GND) B18.C2(GND) B19.C2(GND) B20.C2(GND) B21.C2(GND) B22.C2(GND) B23.C2(GND) B24.C2(GND) B25.C2(GND) B26.C2(GND) B28.C2(GND) B29.C2(GND) B30.C2(GND) B31.C2(GND) B32.C2(GND) B33.C2(GND) B34.C2(GND) B35.C2(GND) B36.C2(GND) B37.C2(GND) B38.C2(GND) B39.C2 B39.F2 B39.J2 B39.L2 B39.N2 B39.R2 B39.U2 B40.C2(GND) C03.C2(GND) C04.C2(GND) C05.C2(GND) C06.C2(GND) C07.C2(GND) C08.C2(GND) C09.C2(GND) C10.C2(GND) C11.C2(GND) C12.C2(GND) C13.C2(GND) C14.C2(GND) C15.C2(GND) C16.C2(GND) C17.C2(GND) C18.C2(GND) C19.C2(GND) C20.C2(GND) C21.C2(GND) C22.C2(C2:GND) C22.T2(T:GND) C22.U2(U:GND) C23.C2(GND) C24.C2(GND) C25.C2(C2:GND) C25.T2(T:GND) C25.U2(U:GND) C26.C2(GND) C27.C2(C2:GND) C27.T2(T:GND) C27.U2(U:GND) C29.C2(GND) C30.C2(GND) C31.C2(GND) C32.C2(GND) C33.C2 C34.C2 C35.C2 C36.C2(GND) C37.C2(GND) C39.C2(GND) C39.V2(V:GND) C40.C2(GND) D03.C2(GND) D04.C2(GND) D05.C2(GND) D06.C2(GND) D07.C2(GND) D08.C2(GND) D09.C2(GND) D10.C2(GND) D11.C2(GND) D12.C2(GND) D13.C2(GND) D14.C2(GND) D15.C2(GND) D16.C2(GND) D17.C2(GND) D18.C2(GND) D19.C2(GND) D20.C2(GND) D21.C2(GND) D22.C2(GND) D23.C2 D24.C2 D25.C2 D26.C2 D27.C2(GND) D29.C2(GND) D30.C2(GND) D31.C2(GND) D32.C2(GND) D33.C2 D34.C2 D35.C2 D36.C2(GND) D37.C2(GND) D38.C2(GND) D39.C2(GND) D40.C2 D40.F2 D40.J2 D40.L2 D40.N2 D40.R2 D40.U2 E03.C2(GND) E04.C2(GND) E05.C2(GND) E05.V2(V:GND) E06.C2(GND) E07.C2(GND) E08.C2(GND) E09.C2(GND) E10.C2(GND) E11.C2(GND) E12.C2(GND) E13.C2(GND) E14.C2(GND) E15.C2(GND) E16.C2(GND) E17.C2(GND) E18.C2(GND) E19.C2(GND) E20.C2(GND) E21.C2 E22.C2(GND) E23.C2(GND) E24.C2(GND) E25.C2(GND) E26.C2 E27.C2 E28.C2 E29.C2(GND) E30.C2 E30.F2 E30.J2 E30.L2 E30.N2 E30.R2 E30.U2 E31.C2 E31.F2 E31.J2 E31.L2 E31.N2 E31.R2 E31.U2 E32.C2 E32.F2 E32.J2 E32.L2 E32.N2 E32.R2 E32.U2 E33.C2 E34.C2 E35.C2 E36.C2(GND) E37.C2 E37.F2 E37.J2 E37.L2 E37.N2 E37.R2 E37.U2 E38.C2 E38.F2 E38.J2 E38.L2 E38.N2 E38.R2 E38.U2 E39.C2 E39.F2 E39.J2 E39.L2 E39.N2 E39.R2 E39.U2 E40.C2 E40.F2 E40.J2 E40.L2 E40.N2 E40.R2 E40.U2 F03.C2(GND) F04.C2(GND) F05.C2(GND) F06.C2(GND) F07.C2(GND) F08.C2(GND) F09.C2(GND) F10.C2(GND) F11.C2(GND) F12.C2(GND) F13.C2(GND) F14.C2(GND) F15.C2(GND) F16.C2(GND) F17.C2(GND) F18.C2(GND) F19.C2(GND) F20.C2(GND) F21.C2 F22.C2(GND) F23.C2(GND) F24.C2(GND) F25.C2(GND) F26.C2 F27.C2 F28.C2 F29.C2 F29.F2 F29.J2 F29.L2 F29.N2 F29.R2 F29.U2 F30.C2 F30.F2 F30.J2 F30.L2 F30.N2 F30.R2 F30.U2 F31.C2 F31.F2 F31.J2 F31.L2 F31.N2 F31.R2 F31.U2 F32.C2 F32.F2 F32.J2 F32.L2 F32.N2 F32.R2 F32.U2 F33.C2 F34.C2 F35.C2 F36.C2(GND) F40.C2(GND)
VCC: A03.A2(VCC) A04.A2(VCC) A05.A2(VCC) A06.A2(VCC) A07.A2(VCC) A08.A2(VCC) A09.A2(VCC) A10.A2(VCC) A11.A2(VCC) A12.A2(VCC) A13.A2(VCC) A14.A2(VCC) A15.A2(VCC) A16.A2(VCC) A17.A2(VCC) A18.A2(VCC) A19.A2(VCC) A20.A2(VCC) A21.A2(VCC) A22.A2(VCC) A23.A2(VCC) A24.A2(VCC) A25.A2(VCC) A26.A2(VCC) A27.A2(VCC) A28.A2(VCC) A29.A2(VCC) A30.A2(VCC) A31.A2(VCC) A32.A2(VCC) A33.A2(VCC) A34.A2(VCC) A35.A2(VCC) A36.A2(VCC) A37.A2(VCC) A38.A2(VCC) A39.A2(VCC) A40.A2(VCC) B03.A2(VCC) B04.A2(VCC) B05.A2(VCC) B06.A2(VCC) B07.A2(VCC) B08.A2(VCC) B09.A2(VCC) B10.A2(VCC) B11.A2(VCC) B12.A2(VCC) B13.A2(VCC) B14.A2(VCC) B15.A2(VCC) B16.A2(VCC) B17.A2(VCC) B18.A2(VCC) B19.A2(VCC) B20.A2(VCC) B21.A2(VCC) B22.A2(VCC) B23.A2(VCC) B24.A2(VCC) B25.A2(VCC) B26.A2(VCC) B27.A2(VCC) B28.A2(VCC) B29.A2(VCC) B30.A2(VCC) B31.A2(VCC) B32.A2(VCC) B33.A2(VCC) B34.A2(VCC) B35.A2(VCC) B36.A2(VCC) B37.A2(VCC) B38.A2(VCC) B40.A2(VCC) C03.A2(VCC) C04.A2(VCC) C05.A2(VCC) C06.A2(VCC) C07.A2(VCC) C08.A2(VCC) C09.A2(VCC) C10.A2(VCC) C11.A2(VCC) C12.A2(VCC) C13.A2(VCC) C14.A2(VCC) C15.A2(VCC) C16.A2(VCC) C17.A2(VCC) C18.A2(VCC) C19.A2(VCC) C20.A2(VCC) C21.A2(VCC) C22.A2(C2:VCC) C23.A2(VCC) C24.A2(VCC) C25.A2(C2:VCC) C26.A2(VCC) C27.A2(C2:VCC) C29.A2(VCC) C30.A2(VCC) C31.A2(VCC) C32.A2(VCC) C33.A2 C34.A2 C35.A2 C36.A2(VCC) C37.A2(VCC) C38.A2(VCC) C39.A2(VCC) C40.A2(VCC) D03.A2(VCC) D04.A2(VCC) D05.A2(VCC) D06.A2(VCC) D07.A2(VCC) D08.A2(VCC) D09.A2(VCC) D10.A2(VCC) D11.A2(VCC) D12.A2(VCC) D13.A2(VCC) D14.A2(VCC) D15.A2(VCC) D16.A2(VCC) D17.A2(VCC) D18.A2(VCC) D19.A2(VCC) D20.A2(VCC) D21.A2(VCC) D22.A2(VCC) D23.A2 D24.A2 D25.A2 D26.A2 D27.A2(VCC) D29.A2(VCC) D30.A2(VCC) D31.A2(VCC) D32.A2(VCC) D33.A2 D34.A2 D35.A2 D36.A2(VCC) D37.A2(VCC) D38.A2(VCC) D39.A2(VCC) E03.A2(VCC) E04.A2(VCC) E05.A2(VCC) E06.A2(VCC) E07.A2(VCC) E08.A2(VCC) E09.A2(VCC) E10.A2(VCC) E11.A2(VCC) E12.A2(VCC) E13.A2(VCC) E14.A2(VCC) E15.A2(VCC) E16.A2(VCC) E17.A2(VCC) E18.A2(VCC) E19.A2(VCC) E20.A2(VCC) E21.A2 E22.A2(VCC) E23.A2(VCC) E24.A2(VCC) E25.A2(VCC) E26.A2 E27.A2 E28.A2 E29.A2(VCC) E33.A2 E34.A2 E35.A2 E36.A2(VCC) F03.A2(VCC) F04.A2(VCC) F05.A2(VCC) F06.A2(VCC) F07.A2(VCC) F08.A2(VCC) F09.A2(VCC) F10.A2(VCC) F11.A2(VCC) F12.A2(VCC) F13.A2(VCC) F14.A2(VCC) F15.A2(VCC) F16.A2(VCC) F17.A2(VCC) F18.A2(VCC) F19.A2(VCC) F20.A2(VCC) F21.A2 F22.A2(VCC) F23.A2(VCC) F24.A2(VCC) F25.A2(VCC) F26.A2 F27.A2 F28.A2 F33.A2 F34.A2 F35.A2 F36.A2(VCC) F37.A2(VCC) F38.A2(VCC) F39.A2(VCC) F40.A2(VCC)

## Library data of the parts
A01 A02 B01 B02 C01 C02 C28 D01 D02 D28 E01 E02 F01 F02 = dec-r:W023: One-sided 18 pin connector/cable.
A03 A22 A33 A35 C11 E03 F06 F16 = dec-r:R001: 7 Diodes
A04 A29-A32 B04 B09 B10-B12 B28 B34 B35 C04 C15-C20 C29-C32 D04 D11-D16 D19 D20 D38 E04 E06 E12 E15-E20 E23-E25 F03-F05 F23 = dec-r:R202: Dual Flip-Flop
A05-A07 B03 B06 B07 C03 C06 D03 E07 = dec-r:W050: Indicator Driver
A08 A10 A15 A26 A27 B15 B17 B24 B25 B36 C14 D06-D08 D32 E09 E10 E11 E13 E14 E36 F14 F36 = dec-r:R113: Diode Gate
A09 A17 A18 A24 A40 B08 B16 B33 B37 C05 C09 C13 C21 C24 C36 D05 D18 D29 F10-F13 F18-F20 F24 F25 = dec-r:R107: 7 Inverters
A11 A14 A21 A23 A25 A34 A38 B13 B20 B23 C07 C10 C12 D36 E29 F07-F09 F15 F17 F40 = dec-r:R111: Diode Gate
A12 A13 A39 B14 B21 B26 C08 D39 = dec-r:R002: 5 Diode Networks
A16 A28 A37 B27 C38 F37-F39 = dec-r:R602: Dual Pulse Amplifier
A19 A20 B18 B19 B22 B29-B31 B38 C37 D09 D10 D31 = dec-r:R603: Triple Pulse Amplifier
A36 D37 = dec-r:R302: Dual Delay (One Shot)
B05 B40 E08 F22 = dec-r:W005: 15 Clamped Loads
B32 D30 E22 = dec-r:R401: Variable Frequency Clock
B39 D40 E37-E40 = dec-r:W028: One-sided 9 pin connector/cable with grounds (Negibus).
C22 C25 C27 = dec-r:M517: M517 Negative Bus Converter
C23 C26 = dec-r:W512: Positive Level Converter
C33-C35 D23-D26 D33-D35 E21 E26-E28 E33-E35 F21 F26-F28 F33-F35 = dec-r:EMPTY: Empty Slot
C39 E05 = dec-r:W501: Negative Input Converter and Schmidt Trigger
C40 = dec-r:W506: Power Monitor
D17 = dec-r:R151: Binary-to-Octal Decoder
D21 D22 D27 = dec-r:M507: M507 Negative Bus Converter
E30-E32 F29-F32 = dec-r:W021: One-sided 9 pin connector/cable with grounds (Negibus).

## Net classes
1 Supply: width 0.635 mm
